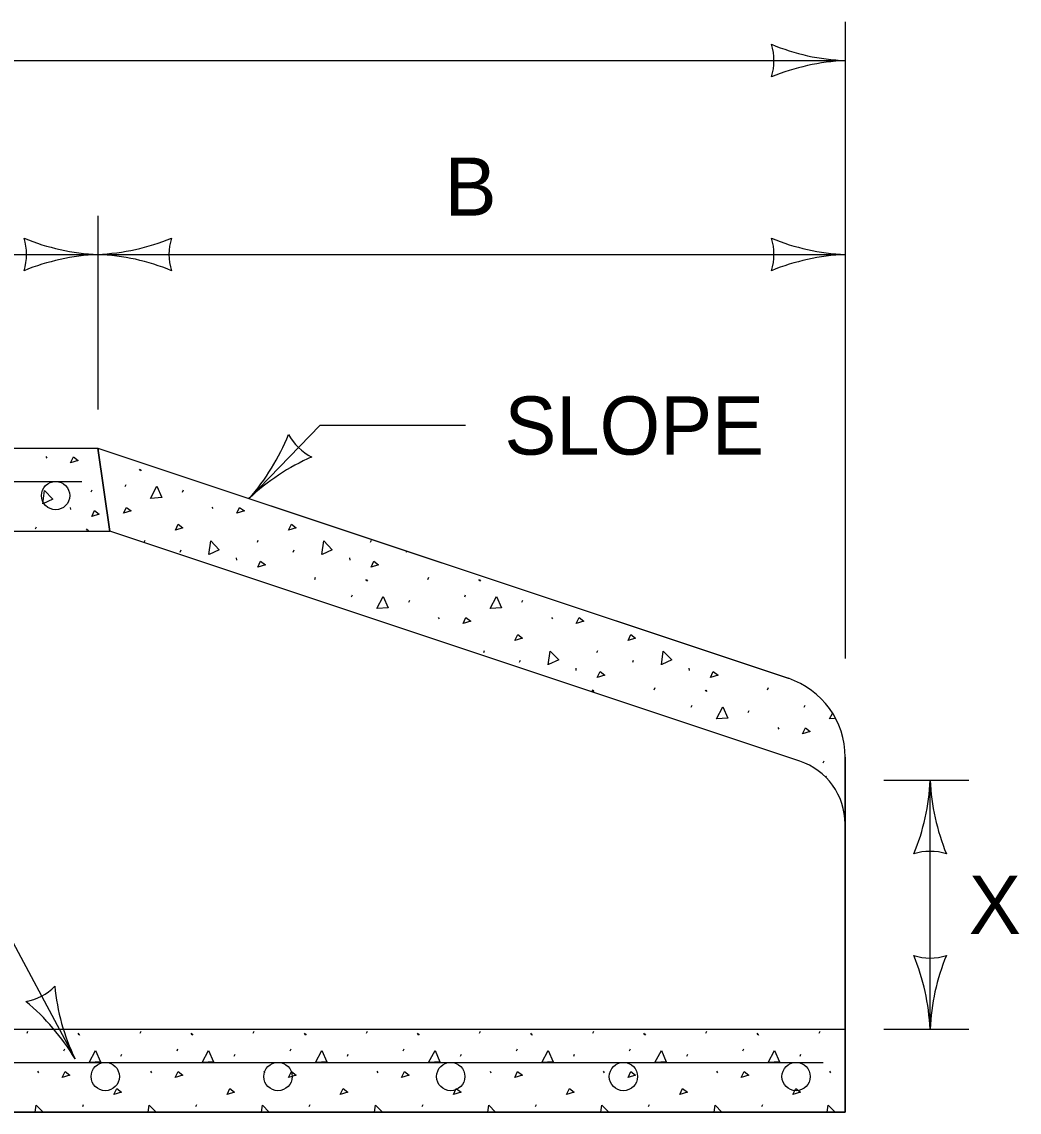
# Model space of a CAD drawing. Extents: x 49991.4 to 50021, y 49987.6 to 50011.4.
# Drawn here: x 50001.918 to 50002.946, y 49995.4 to 49996.525 of the extents above; entities that cross this region are included whole.
import ezdxf

# ---------------------------------------------------------------- set-up
doc = ezdxf.new("R2010")
doc.units = 0
for name, color, linetype in [('Level 1', 7, 'Continuous'), ('Level 2', 7, 'Continuous'), ('Level 3', 7, 'Continuous')]:
    doc.layers.add(name, color=color, linetype=linetype)

msp = doc.modelspace()

# ---------------------------------------------------------------- linework, layer by layer
at = {"layer": 'Level 1'}
for p, q in [((50000.6836, 49996.0847), (50001.9962, 49996.0847)), ((50001.9962, 49996.0847), (50002.7083, 49995.8474)), ((50001.9962, 49996.0847), (50002.0087, 49995.999)), ((50001.9962, 49996.0847), (50002.0087, 49995.999)), ((50002.0087, 49995.999), (50001.9962, 49996.0847)), ((50001.9962, 49996.0847), (50002.7082, 49995.8474)), ((50001.9962, 49996.0847), (50002.0087, 49995.999)), ((50001.9426, 49996.0761), (50001.9436, 49996.0747)), ((50002.0389, 49996.0633), (50002.0398, 49996.0618)), ((50002.0398, 49996.0627), (50002.0408, 49996.0613)), ((50002.0245, 49996.0452), (50002.0255, 49996.0474)), ((50001.9894, 49996.0398), (50001.9904, 49996.042)), ((50002.0834, 49996.0396), (50002.0844, 49996.0418)), ((50001.9677, 49996.0237), (50001.9679, 49996.0215)), ((50002.1139, 49996.024), (50002.1149, 49996.0226)), ((50001.9319, 49996.0016), (50001.9329, 49996.0038)), ((50001.9843, 49996.0016), (50001.9853, 49996.0001)), ((50001.9853, 49996.001), (50001.9862, 49995.9996)), ((50002.0087, 49995.999), (50000.7692, 49995.999)), ((50002.72, 49995.762), (50002.0087, 49995.9992)), ((50002.0087, 49995.9992), (50002.0087, 49995.999)), ((50002.72, 49995.762), (50002.0087, 49995.9992)), ((50002.044, 49995.9877), (50002.045, 49995.9899)), ((50002.1607, 49995.9877), (50002.1616, 49995.9899)), ((50002.2774, 49995.9877), (50002.2783, 49995.9899)), ((50002.081, 49995.9777), (50002.082, 49995.9799)), ((50002.1977, 49995.9777), (50002.1987, 49995.9799)), ((50002.3144, 49995.9777), (50002.3148, 49995.9785)), ((50002.1389, 49995.9716), (50002.1392, 49995.9694)), ((50002.2556, 49995.9716), (50002.2559, 49995.9694)), ((50002.2199, 49995.9495), (50002.2208, 49995.9517)), ((50002.2722, 49995.9495), (50002.2732, 49995.948)), ((50002.2732, 49995.9489), (50002.2742, 49995.9475)), ((50002.3366, 49995.9495), (50002.3375, 49995.9517)), ((50002.3889, 49995.9495), (50002.3899, 49995.948)), ((50002.3899, 49995.9489), (50002.3909, 49995.9475)), ((50002.2579, 49995.9314), (50002.2588, 49995.9336)), ((50002.3746, 49995.9314), (50002.3755, 49995.9336)), ((50002.3168, 49995.9258), (50002.3178, 49995.928)), ((50002.4335, 49995.9258), (50002.4345, 49995.928)), ((50002.3473, 49995.9102), (50002.3483, 49995.9088)), ((50002.464, 49995.9102), (50002.4649, 49995.9088)), ((50002.3941, 49995.8739), (50002.395, 49995.8761)), ((50002.4311, 49995.864), (50002.4321, 49995.8661)), ((50002.5107, 49995.8739), (50002.5117, 49995.8761)), ((50002.5478, 49995.864), (50002.5487, 49995.8661)), ((50002.6274, 49995.8739), (50002.6276, 49995.8743)), ((50002.489, 49995.8578), (50002.4892, 49995.8556)), ((50002.6057, 49995.8578), (50002.6059, 49995.8556)), ((50002.5056, 49995.8357), (50002.5066, 49995.8342)), ((50002.5066, 49995.8351), (50002.5076, 49995.8337)), ((50002.5699, 49995.8357), (50002.5709, 49995.8379)), ((50002.6223, 49995.8357), (50002.6233, 49995.8342)), ((50002.6233, 49995.8351), (50002.6243, 49995.8337)), ((50002.6866, 49995.8357), (50002.6876, 49995.8379)), ((50002.6079, 49995.8176), (50002.6089, 49995.8198)), ((50002.6669, 49995.812), (50002.6679, 49995.8142)), ((50002.7246, 49995.8176), (50002.7256, 49995.8198)), ((50002.6973, 49995.7965), (50002.6983, 49995.795)), ((50002.7668, 49995.4854), (50002.7668, 49995.7662)), ((50002.7668, 49995.7662), (50002.7668, 49995.3998)), ((50002.7668, 49995.3998), (50002.7668, 49995.7662)), ((50002.7668, 49995.3998), (50002.7668, 49995.7657)), ((50002.7441, 49995.7602), (50002.7451, 49995.7623)), ((50002.7464, 49995.7465), (50002.7471, 49995.7455)), ((50000.7692, 49995.4854), (50002.7668, 49995.4854)), ((50001.9232, 49995.4812), (50001.9241, 49995.4834)), ((50002.0398, 49995.4812), (50002.0408, 49995.4834)), ((50002.1565, 49995.4812), (50002.1575, 49995.4834)), ((50002.2732, 49995.4812), (50002.2742, 49995.4834)), ((50002.3899, 49995.4812), (50002.3909, 49995.4834)), ((50002.5066, 49995.4812), (50002.5076, 49995.4834)), ((50002.6233, 49995.4812), (50002.6243, 49995.4834)), ((50002.74, 49995.4812), (50002.741, 49995.4834)), ((50002.7668, 49995.4854), (50002.7668, 49995.3998)), ((50001.9755, 49995.4812), (50001.9765, 49995.4797)), ((50001.9765, 49995.4806), (50001.9775, 49995.4792)), ((50002.0922, 49995.4812), (50002.0932, 49995.4797)), ((50002.0932, 49995.4806), (50002.0942, 49995.4792)), ((50002.2089, 49995.4812), (50002.2099, 49995.4797)), ((50002.2099, 49995.4806), (50002.2109, 49995.4792)), ((50002.3256, 49995.4812), (50002.3266, 49995.4797)), ((50002.3266, 49995.4806), (50002.3276, 49995.4792)), ((50002.4423, 49995.4812), (50002.4433, 49995.4797)), ((50002.4433, 49995.4806), (50002.4442, 49995.4792)), ((50002.559, 49995.4812), (50002.56, 49995.4797)), ((50002.56, 49995.4806), (50002.5609, 49995.4792)), ((50002.6757, 49995.4812), (50002.6766, 49995.4797)), ((50002.6766, 49995.4806), (50002.6776, 49995.4792)), ((50001.9612, 49995.4631), (50001.9621, 49995.4653)), ((50002.0779, 49995.4631), (50002.0788, 49995.4653)), ((50002.1945, 49995.4631), (50002.1955, 49995.4653)), ((50002.3112, 49995.4631), (50002.3122, 49995.4653)), ((50002.4279, 49995.4631), (50002.4289, 49995.4653)), ((50002.5446, 49995.4631), (50002.5456, 49995.4653)), ((50002.6613, 49995.4631), (50002.6623, 49995.4653)), ((50002.0201, 49995.4575), (50002.0211, 49995.4597)), ((50002.1368, 49995.4575), (50002.1378, 49995.4597)), ((50002.2535, 49995.4575), (50002.2545, 49995.4597)), ((50002.3702, 49995.4575), (50002.3712, 49995.4597)), ((50002.4869, 49995.4575), (50002.4878, 49995.4597)), ((50002.6036, 49995.4575), (50002.6045, 49995.4597)), ((50002.7203, 49995.4575), (50002.7212, 49995.4597)), ((50001.9339, 49995.442), (50001.9349, 49995.4405)), ((50002.0506, 49995.442), (50002.0515, 49995.4405)), ((50002.1673, 49995.442), (50002.1682, 49995.4405)), ((50002.2839, 49995.442), (50002.2849, 49995.4405)), ((50002.4006, 49995.442), (50002.4016, 49995.4405)), ((50002.5173, 49995.442), (50002.5183, 49995.4405)), ((50002.634, 49995.442), (50002.635, 49995.4405)), ((50002.7507, 49995.442), (50002.7517, 49995.4405)), ((50001.9807, 49995.4057), (50001.9816, 49995.4078)), ((50002.0973, 49995.4057), (50002.0983, 49995.4078)), ((50002.214, 49995.4057), (50002.215, 49995.4078)), ((50002.3307, 49995.4057), (50002.3317, 49995.4078)), ((50002.4474, 49995.4057), (50002.4484, 49995.4078)), ((50002.5641, 49995.4057), (50002.5651, 49995.4078)), ((50002.6808, 49995.4057), (50002.6818, 49995.4078)), ((50000.6836, 49995.3998), (50002.7668, 49995.3998)), ((50000.6836, 49995.3998), (50002.7668, 49995.3998)), ((50002.7668, 49995.3998), (50000.6836, 49995.3998)), ((50002.7668, 49995.3998), (50000.6836, 49995.3998)), ((50002.7668, 49995.3998), (50000.6836, 49995.3998)), ((50002.7668, 49995.3998), (50000.6836, 49995.3998)), ((50002.76, 49995.3998), (50002.7601, 49995.4))]:
    msp.add_line(p, q, dxfattribs=at)
for points in [[(50001.9682, 49996.0698), (50001.9711, 49996.0759), (50001.976, 49996.0722), (50001.9682, 49996.0698)], [(50000.7828, 49996.0504), (50001.9796, 49996.0504)], [(50001.9394, 49996.0273), (50001.9413, 49996.0413), (50001.95, 49996.0323), (50001.9396, 49996.0274)], [(50002.0506, 49996.033), (50002.0571, 49996.0455), (50002.0623, 49996.034), (50002.0508, 49996.033)], [(50002.0228, 49996.0177), (50002.0257, 49996.0238), (50002.0306, 49996.0201), (50002.0228, 49996.0177)], [(50002.1395, 49996.0177), (50002.1424, 49996.0238), (50002.1473, 49996.0201), (50002.1395, 49996.0177)], [(50001.9899, 49996.0143), (50001.9928, 49996.0204), (50001.9977, 49996.0167), (50001.9899, 49996.0143)], [(50002.0762, 49996.0003), (50002.0791, 49996.0064), (50002.084, 49996.0027), (50002.0762, 49996.0003)], [(50002.1929, 49996.0003), (50002.1958, 49996.0064), (50002.2007, 49996.0027), (50002.1929, 49996.0003)], [(50002.1106, 49995.9752), (50002.1126, 49995.9892), (50002.1213, 49995.9801), (50002.1109, 49995.9753)], [(50002.2273, 49995.9752), (50002.2293, 49995.9892), (50002.238, 49995.9801), (50002.2276, 49995.9753)], [(50002.1612, 49995.9622), (50002.1641, 49995.9682), (50002.169, 49995.9646), (50002.1612, 49995.9622)], [(50002.2779, 49995.9622), (50002.2808, 49995.9682), (50002.2856, 49995.9646), (50002.2779, 49995.9622)], [(50002.2839, 49995.9193), (50002.2905, 49995.9317), (50002.2956, 49995.9202), (50002.2842, 49995.9193)], [(50002.4006, 49995.9193), (50002.4072, 49995.9317), (50002.4123, 49995.9202), (50002.4009, 49995.9193)], [(50002.3729, 49995.9039), (50002.3758, 49995.91), (50002.3807, 49995.9063), (50002.3729, 49995.9039)], [(50002.4895, 49995.9039), (50002.4925, 49995.91), (50002.4973, 49995.9063), (50002.4895, 49995.9039)], [(50002.4263, 49995.8865), (50002.4292, 49995.8926), (50002.4341, 49995.8889), (50002.4263, 49995.8865)], [(50002.5429, 49995.8865), (50002.5459, 49995.8926), (50002.5507, 49995.8889), (50002.5429, 49995.8865)], [(50002.4607, 49995.8614), (50002.4626, 49995.8754), (50002.4714, 49995.8664), (50002.4609, 49995.8615)], [(50002.5774, 49995.8614), (50002.5793, 49995.8754), (50002.5881, 49995.8664), (50002.5776, 49995.8615)], [(50002.5112, 49995.8484), (50002.5142, 49995.8545), (50002.519, 49995.8508), (50002.5112, 49995.8484)], [(50002.6279, 49995.8484), (50002.6308, 49995.8545), (50002.6357, 49995.8508), (50002.6279, 49995.8484)], [(50002.634, 49995.8055), (50002.6406, 49995.8179), (50002.6457, 49995.8064), (50002.6343, 49995.8055)], [(50002.7507, 49995.8055), (50002.7536, 49995.811)], [(50002.7559, 49995.8059), (50002.7509, 49995.8055)], [(50002.7229, 49995.7901), (50002.7258, 49995.7962), (50002.7307, 49995.7926), (50002.7229, 49995.7901)], [(50001.9872, 49995.451), (50001.9938, 49995.4634), (50001.9989, 49995.4519), (50001.9875, 49995.451)], [(50002.1039, 49995.451), (50002.1105, 49995.4634), (50002.1156, 49995.4519), (50002.1042, 49995.451)], [(50002.2206, 49995.451), (50002.2272, 49995.4634), (50002.2323, 49995.4519), (50002.2209, 49995.451)], [(50002.3373, 49995.451), (50002.3439, 49995.4634), (50002.349, 49995.4519), (50002.3375, 49995.451)], [(50002.454, 49995.451), (50002.4606, 49995.4634), (50002.4657, 49995.4519), (50002.4542, 49995.451)], [(50002.5707, 49995.451), (50002.5773, 49995.4634), (50002.5824, 49995.4519), (50002.5709, 49995.451)], [(50002.6874, 49995.451), (50002.6939, 49995.4634), (50002.6991, 49995.4519), (50002.6876, 49995.451)], [(50000.7853, 49995.4512), (50002.7442, 49995.4512)], [(50001.9595, 49995.4356), (50001.9624, 49995.4417), (50001.9673, 49995.4381), (50001.9595, 49995.4356)], [(50002.0761, 49995.4356), (50002.0791, 49995.4417), (50002.0839, 49995.4381), (50002.0761, 49995.4356)], [(50002.1928, 49995.4356), (50002.1958, 49995.4417), (50002.2006, 49995.4381), (50002.1928, 49995.4356)], [(50002.3095, 49995.4356), (50002.3124, 49995.4417), (50002.3173, 49995.4381), (50002.3095, 49995.4356)], [(50002.4262, 49995.4356), (50002.4291, 49995.4417), (50002.434, 49995.4381), (50002.4262, 49995.4356)], [(50002.5429, 49995.4356), (50002.5458, 49995.4417), (50002.5507, 49995.4381), (50002.5429, 49995.4356)], [(50002.6596, 49995.4356), (50002.6625, 49995.4417), (50002.6674, 49995.4381), (50002.6596, 49995.4356)], [(50002.0129, 49995.4182), (50002.0158, 49995.4243), (50002.0207, 49995.4206), (50002.0129, 49995.4182)], [(50002.1295, 49995.4182), (50002.1325, 49995.4243), (50002.1373, 49995.4206), (50002.1295, 49995.4182)], [(50002.2462, 49995.4182), (50002.2492, 49995.4243), (50002.254, 49995.4206), (50002.2462, 49995.4182)], [(50002.3629, 49995.4182), (50002.3658, 49995.4243), (50002.3707, 49995.4206), (50002.3629, 49995.4182)], [(50002.4796, 49995.4182), (50002.4825, 49995.4243), (50002.4874, 49995.4206), (50002.4796, 49995.4182)], [(50002.5963, 49995.4182), (50002.5992, 49995.4243), (50002.6041, 49995.4206), (50002.5963, 49995.4182)], [(50002.713, 49995.4182), (50002.7159, 49995.4243), (50002.7208, 49995.4206), (50002.713, 49995.4182)], [(50001.9316, 49995.3998), (50001.9326, 49995.4071), (50001.9397, 49995.3998)], [(50002.0482, 49995.3998), (50002.0492, 49995.4071), (50002.0563, 49995.3998)], [(50002.1649, 49995.3998), (50002.1659, 49995.4071), (50002.173, 49995.3998)], [(50002.2816, 49995.3998), (50002.2826, 49995.4071), (50002.2897, 49995.3998)], [(50002.3983, 49995.3998), (50002.3993, 49995.4071), (50002.4064, 49995.3998)], [(50002.515, 49995.3998), (50002.516, 49995.4071), (50002.5231, 49995.3998)], [(50002.6317, 49995.3998), (50002.6327, 49995.4071), (50002.6398, 49995.3998)], [(50002.7484, 49995.3998), (50002.7494, 49995.4071), (50002.7565, 49995.3998)]]:
    msp.add_lwpolyline(points, dxfattribs=at)
for centre in [(50001.9527, 49996.0359), (50002.0039, 49995.4366), (50002.182, 49995.4366), (50002.3601, 49995.4366), (50002.5382, 49995.4366), (50002.7162, 49995.4366)]:
    msp.add_circle(centre, 0.0146, dxfattribs=at)
for centre, radius, end in [((50002.6812, 49995.7662), 0.0856, 71.5726), ((50002.6812, 49995.7662), 0.0856, 71.5726), ((50002.6983, 49995.697), 0.0685, 71.5723), ((50002.6983, 49995.697), 0.0685, 71.5723)]:
    msp.add_arc(centre, radius, 0, end, dxfattribs=at)
at = {"layer": 'Level 3'}
for p, q in [((50002.7668, 49996.5247), (50002.7668, 49996.0522)), ((50000.6836, 49996.4847), (50002.7668, 49996.4847)), ((50001.9962, 49996.3247), (50001.9962, 49996.1247)), ((50000.6836, 49996.2847), (50001.9962, 49996.2847)), ((50001.9962, 49996.2847), (50002.7668, 49996.2847)), ((50002.225, 49996.1082), (50002.1521, 49996.0328)), ((50002.3755, 49996.1082), (50002.225, 49996.1082)), ((50002.7668, 49996.0522), (50002.7668, 49995.8679)), ((50002.8068, 49995.7423), (50002.8944, 49995.7423)), ((50002.8544, 49995.4854), (50002.8544, 49995.7423)), ((50001.8874, 49995.6147), (50001.9727, 49995.4548)), ((50002.8068, 49995.4854), (50002.8944, 49995.4854))]:
    msp.add_line(p, q, dxfattribs=at)
for centre, radius, start, end in [((50002.776, 49996.7068), 0.2223, 247.456, 267.6395), ((50002.6386, 49996.4847), 0.0548, 342.1388, 17.8612), ((50002.7783, 49996.252), 0.233, 92.8273, 112.0772), ((50002.0054, 49996.5068), 0.2223, 247.456, 267.6395), ((50001.868, 49996.2847), 0.0548, 342.1388, 17.8612), ((50001.9847, 49996.5174), 0.233, 272.8273, 292.0772), ((50002.1244, 49996.2847), 0.0548, 162.1388, 197.8612), ((50002.776, 49996.5068), 0.2223, 247.456, 267.6395), ((50002.6386, 49996.2847), 0.0548, 342.1388, 17.8612), ((50002.0077, 49996.052), 0.233, 92.8273, 112.0772), ((50001.987, 49996.0626), 0.2223, 67.456, 87.6395), ((50002.7783, 49996.052), 0.233, 92.8273, 112.0772), ((50001.9768, 49996.1862), 0.233, 318.801, 338.0508), ((50002.2412, 49996.1249), 0.0548, 208.1125, 243.8348), ((50002.3054, 49995.8718), 0.2223, 113.4297, 133.6132), ((50002.6323, 49995.7515), 0.2223, 337.456, 357.6395), ((50003.0871, 49995.7538), 0.233, 182.8273, 202.0772), ((50002.8544, 49995.6141), 0.0548, 72.1388, 107.8612), ((50002.8544, 49995.6136), 0.0548, 252.1388, 287.8612), ((50002.6217, 49995.4739), 0.233, 2.8273, 22.0772), ((50003.0765, 49995.4762), 0.2223, 157.456, 177.6395), ((50001.9124, 49995.5679), 0.0548, 280.2056, 315.928), ((50002.173, 49995.5512), 0.2223, 185.5228, 205.7063), ((50001.7728, 49995.3352), 0.233, 30.8941, 50.144)]:
    msp.add_arc(centre, radius, start, end, dxfattribs=at)

# ---------------------------------------------------------------- texts
at = {"layer": 'Level 2'}
for s, p in [('B', (50002.3538, 49996.3247)), ('SLOPE', (50002.4155, 49996.0782)), ('X', (50002.8944, 49995.5838))]:
    msp.add_text(s, height=0.06, dxfattribs=at).set_placement(p)

doc.saveas('drawing.dxf')
